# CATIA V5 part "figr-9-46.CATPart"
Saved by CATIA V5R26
Part number: Part1
Bounding box of the stored display mesh (mm): x -159.661 to 182.627, y -78.048 to 78.048, z 0 to 72.429
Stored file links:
  D:\_Deepak\CATIA\CATIA V5-6R2016_Deepak\Resources\Part files\Partfiles\c09_catia_v5_6r2016_prt\figr-9-46.CATPart
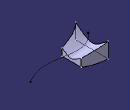
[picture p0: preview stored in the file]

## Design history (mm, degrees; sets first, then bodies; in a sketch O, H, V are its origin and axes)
Body1 (main body)
  Plane1: type Offset, RefPlane yz-plane, Offset 100
  Plane2: type Offset, RefPlane yz-plane, Offset 100, reversed
  Sketch1 on Plane1, origin (100, 0, 0), H (0, 1, 0), V (0, 0, 1)
    point P1 (0, 15.965)
    hyperbola C1
    point P2 (0, 3.0416)
    line L1 (54.8261, 44.8858) -> (54.8261, 0)
    point P5 (54.8261, 0)
    line L2 (-54.8261, 44.8858) -> (-54.8261, 0)
    point P6 (-54.8261, 0)
    line L3 (-54.8261, 0) -> (54.8261, 0)
    coincidence: P1 V, P2 V, P5 H, P6 H
    vertical: L1 V, L2 V
    horizontal: L3 H
  Sketch2 on xy-plane, origin (0, 0, 0), H (1, 0, 0), V (0, 1, 0)
    spline S1 through (-159.6608, -77.1468) (-77.8466, -31.8169) (23.6283, -41.4968) (182.6271, -11.7333)
  Sketch3 on yz-plane, origin (0, 0, 0), H (0, 1, 0), V (0, 0, 1)
    point P1 (0, 18.9787)
    hyperbola C1
    point P2 (0, 2.6681)
    line L1 (48.2237, 37.1764) -> (48.2237, 0)
    point P5 (48.2237, 0)
    line L2 (-43.6563, 34.1546) -> (-43.6563, 0)
    point P6 (-43.6563, 0)
    line L3 (-43.6563, 0) -> (48.2237, 0)
    coincidence: P1 V, P2 V, P5 H, P6 H
    vertical: L1 V, L2 V
    horizontal: L3 H
  Sketch4 on Plane2, origin (-100, 0, 0), H (0, 1, 0), V (0, 0, 1)
    point P1 (0, 140.6052)
    point P2 (0, 41.8972)
    hyperbola C1
    line L1 (78.0478, 72.4293) -> (78.0478, 0)
    point P5 (78.0478, 0)
    line L2 (-78.0478, 72.4293) -> (-78.0478, 0)
    point P6 (-78.0478, 0)
    line L3 (-78.0478, 0) -> (78.0478, 0)
    coincidence: P1 V, P2 V, P5 H, P6 H
    vertical: L1 V, L2 V
    horizontal: L3 H
  Loft1: solid, Sections (Sketch3; Sketch4), Spine Sketch2
  Loft2: solid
